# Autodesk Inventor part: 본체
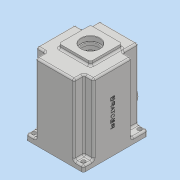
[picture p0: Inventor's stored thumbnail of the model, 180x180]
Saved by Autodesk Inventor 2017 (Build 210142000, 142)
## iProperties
Part Number: 본체
Material: 일반
Document SubType Name: Modeling
Designer: MRC
Density: 1 g/cm^3
Appearance: 기본값
Author: MRC
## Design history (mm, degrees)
sketch "스케치1"
  geometry: L1 (-49, 60)-(49, 60); L2 (49, 60)-(49, -50); L3 (49, -50)-(-49, -50); L4 (-49, -50)-(-49, 60); 2 further points
  constraints: 8 end point, 2 parallel, 1 horizontal, 1 midpoint, 1 perpendicular, 1 vertical alignment
  dimensions: "d0" = 50 distance from line of L3 point (0, 0); "d1" = 110 distance of L1.end L2.end; "d2" = 98 distance of L2.end L3.end
extrude "돌출1" new body sketch "스케치1" stored distance "d3" = 130; taper "d4" = 0 deg
sketch "스케치2"
  geometry: L1 (49, 60)-(-49, 60) reference; L2 (-49, -50)-(49, -50) reference; L3 (49, -50)-(49, 60) reference; L4 (33, 60)-(33, 33); L5 (33, 33)-(49, 33); L6 (49, -33)-(33, -33); L7 (33, -33)-(33, -50); 1 further point
  constraints: 8 end point, 4 point on line, 3 perpendicular, 1 horizontal
  dimensions: "d5" = 16 distance of L4.end L5.end; "d6" = 27 distance of L4.start L4.end; "d7" = 17 distance of L6.end L7.end; "d8" = 16 distance of L6.start L6.end
extrude "돌출2" cut sketch "스케치2" distance "d9" = 120; taper "d10" = 0 deg
sketch "스케치3"
  geometry: L1 (-27, 38)-(27, 38); L2 (27, 38)-(27, -16); L3 (27, -16)-(-27, -16); L4 (-27, -16)-(-27, 38); 2 further points
  constraints: 8 end point, 2 parallel, 1 horizontal, 1 midpoint, 1 perpendicular, 1 vertical alignment
  dimensions: "d87" = 54 distance of L2.end L3.end; "d88" = 54 distance of L1.end L2.end
extrude "돌출12" join sketch "스케치3" distance "d90" = 7; taper "d91" = 0 deg
sketch "스케치4"
  geometry: L1 (-26, 53)-(26, 53); L2 (26, 53)-(26, 36.729); L3 (-26, 53)-(-26, 36.729); A1 r 45 centre (0, 0) between (-26, 36.729) and (26, 36.729); 2 further points
  constraints: 6 end point, 2 point on circle, 2 vertical, 1 centre point, 1 coincident, 1 horizontal, 1 midpoint, 1 vertical alignment
  dimensions: "d15" = 90 diameter of A1; "d16" = 52 distance of L1.start L1.end; "d17" = 53 distance from line of point (0, 0) L1
extrude "돌출4" cut sketch "스케치4" distance "d18" = 9; taper "d19" = 0 deg
sketch "스케치5"
  geometry: L1 (-26, 53)-(26, 53) reference; L2 (-26, 36.729)-(-26, 53) reference; L3 (26, 53)-(26, 36.729) reference; L4 (-26, 53)-(26, 53) reference; L5 (-26, 36.729)-(-26, 53) reference; L6 (26, 53)-(26, 36.729) reference; L7 (23, 50)-(-23, 50); L8 (-23, 50)-(-23, 35.143); L9 (23, 35.143)-(23, 50); A1 r 45 centre (0, 0) between (-26, 36.729) and (26, 36.729) reference; A2 r 45 centre (0, 0) between (-26, 36.729) and (26, 36.729) reference; A3 r 42 centre (0, 0) between (-23, 35.143) and (23, 35.143)
  constraints: 6 end point, 2 point on circle, 1 centre point, 3 other
  dimensions: "d20" = 3 distance between parallel lines of L1 L7
extrude "돌출5" cut sketch "스케치5" distance "d21" = 112; taper "d22" = 0 deg
sketch "스케치6"
  geometry: A1 r 42 centre (0, 0) between (-23, 35.143) and (23, 35.143) reference; A2 r 21 centre (0, 11) between (8.978, -7.984) and (-8.978, -7.984); A3 r 15 centre (0, -20) between (-8.978, -7.984) and (8.978, -7.984)
  constraints: 4 point on circle, 2 centre point, 2 vertical alignment
  dimensions: "d23" = 42 diameter of A2; "d24" = 11 distance of A1.centre A2.centre; "d25" = 30 diameter of A3; "d26" = 20 distance of A3.centre A1.centre
extrude "돌출6" join sketch "스케치6" distance "d27" = 7; taper "d28" = 0 deg
sketch "스케치7"
  geometry: C1 r 17.5 at (0, 11); A1 r 21 centre (0, 11) between (8.978, -7.984) and (-8.978, -7.984) reference; 1 further point
  constraints: 1 centre point, 1 coincident
  dimensions: "d29" = 35 diameter of C1
extrude "돌출7" cut sketch "스케치7" distance "d30" = 10; taper "d31" = 0 deg
sketch "스케치8"
  geometry: C1 r 17.5 at (0, 0) reference; C2 r 14 at (0, 0); 1 further point
  constraints: 1 centre point, 1 coincident
  dimensions: "d32" = 28 diameter of C2
extrude "돌출8" cut sketch "스케치8" stored distance "d33" = 10; taper "d34" = 0 deg
sketch "스케치9"
  geometry: C1 r 11 at (0, -20); A1 r 15 centre (0, -20) between (-8.978, -7.984) and (8.978, -7.984) reference; 1 further point
  constraints: 1 centre point, 1 coincident
  dimensions: "d35" = 22 diameter of C1
extrude "돌출9" cut sketch "스케치9" distance "d36" = 7; taper "d37" = 0 deg
sketch "스케치10"
  geometry: C1 r 11 at (0, 0) reference; C2 r 9.5 at (0, 0); 1 further point
  constraints: 1 centre point, 1 coincident
  dimensions: "d38" = 19 diameter of C2
extrude "돌출10" cut sketch "스케치10" distance "d39" = 3; taper "d40" = 0 deg
fillet "모깎기1" dims "d41" = 3
fillet "모깎기2" dims "d42" = 0.3
chamfer "모따기1" distance "d43" = 1; stored, may be unused: second distance "d44" = 2, angle "d45" = 45 deg
chamfer "모따기2" distance "d46" = 1; stored, may be unused: second distance "d47" = 2, angle "d48" = 45 deg
fillet "모깎기3" dims "d49" = 0.3
sketch "스케치13"
  geometry: L1 (-23, 35.143)-(-23, 50) reference; L2 (23, 50)-(23, 35.143) reference; L3 (-35.777, 4)-(-41.809, 4); L4 (-35.777, -4)-(-41.809, -4); A1 r 36 centre (0, 0) between (-36, 0) and (-35.777, 4); A2 r 4 centre (-36, 0) between (-36, -4) and (-36, 4); A3 r 42 centre (0, 0) between (-41.809, 4) and (-41.809, -4); A4 r 42 centre (0, 0) between (23, 35.143) and (-23, 35.143); 2 further points
  constraints: 9 point on circle, 6 end point, 4 centre point, 2 coincident, 2 horizontal, 2 point on line, 2 tangent, 1 horizontal alignment
  dimensions: "d57" = 72 diameter of A1; "d58" = 8 diameter of A2
extrude "돌출11" join sketch "스케치13" stored distance "d60" = 3; taper "d61" = 0 deg
hole "구멍1" diameter "d64" = 3.242; stored, may be unused: countersink angle "d68" = 90 deg, drill point angle "d70" = 118 deg; dims "d62" = 10, "d63" = 10, "d65" = 7, "d66" = 4, "d67" = 2, "d69" = 9
hole "구멍2" diameter "d73" = 3.242; stored, may be unused: countersink angle "d77" = 90 deg, drill point angle "d79" = 118 deg; dims "d71" = 10, "d72" = 10, "d74" = 7, "d75" = 4, "d76" = 2, "d78" = 9
fillet "모깎기6" dims "d80" = 6
fillet "모깎기7" dims "d81" = 3
fillet "모깎기8" dims "d82" = 3
chamfer "모따기3" distance "d83" = 1; stored, may be unused: second distance "d84" = 2, angle "d85" = 45 deg
fillet "모깎기9" dims "d86" = 3
sketch "스케치15"
  geometry: L1 (11, 63.7)-(11, 72); L2 (11, 72)-(27.462, 72); L3 (-3, 72)-(25, 72) reference; L4 (27.462, 72)-(27, 71.2); L5 (27, 71.2)-(27, 63.7); L6 (27, 63.7)-(11, 63.7); L7 (38, 72)-(-16, 72) reference; 1 further point
  constraints: 10 end point, 1 collinear, 1 midpoint, 1 parallel, 1 perpendicular, 1 point on line, 1 vertical
  dimensions: "d94" = 8.3 distance between parallel lines of L2 L6; "d95" = 0.8 vertical distance of L2.end L4.end; "d96" = 30 deg angle of L5 L4; "d97" = 32 diameter of L5 L1
revolve "회전2" sketch "스케치15" stored, may be unused: angle "d98" = 90 deg
fillet "모깎기10" dims "d99" = 0.3
fillet "모깎기11" dims "d100" = 3
fillet "모깎기12" dims "d101" = 3
fillet "모깎기13" dims "d102" = 3
sketch "스케치16"
  geometry: L1 (-49, 57)-(-49, -47) reference; L2 (46, 60)-(-46, 60) reference; L3 (-46, -50)-(46, -50) reference; L4 (49, -47)-(49, 57) reference; C1 r 3.5 at (-42, 53); C2 r 3.5 at (-42, -43); C3 r 3.5 at (42, -43); C4 r 3.5 at (42, 53)
  constraints: 4 centre point
  dimensions: "d104" = 7 diameter of C1; "d105" = 7 distance from line of L2 C1.centre; "d106" = 7 distance from line of L1 C1.centre; "d109" = 7 diameter of C2; "d110" = 7 diameter of C3; "d111" = 7 diameter of C4; "d112" = 7 distance from line of L3 C2.centre; "d113" = 7 distance from line of L1 C2.centre; "d114" = 7 distance from line of L3 C3.centre; "d115" = 7 distance from line of C3.centre L4; "d116" = 7 distance from line of L2 C4.centre; "d117" = 7 distance from line of L4 C4.centre
extrude "돌출14" cut sketch "스케치16" stored distance "d118" = 7; taper "d119" = 0 deg
sketch "스케치17"
  geometry: L1 (0, 0)-(92, 0) reference; C1 r 22.5 at (46, -40); 2 further points
  constraints: 1 centre point, 1 midpoint, 1 vertical alignment
  dimensions: "d120" = 45 diameter of C1; "d121" = 40 distance from line of L1 C1.centre
extrude "돌출15" join sketch "스케치17" distance "d122" = 10; taper "d123" = 0 deg
sketch "스케치18"
  geometry: C1 r 22.5 at (46, -40) reference; C2 r 15 at (46, -89); 1 further point
  constraints: 1 centre point, 1 vertical alignment
  dimensions: "d124" = 30 diameter of C2; "d125" = 49 distance of C2.centre C1.centre
extrude "돌출16" join sketch "스케치18" distance "d126" = 5; taper "d127" = 0 deg
hole "구멍3" diameter "d130" = 33.376; stored, may be unused: countersink angle "d134" = 90 deg, drill point angle "d136" = 118 deg; dims "d128" = 10, "d129" = 10, "d131" = 70, "d132" = 4, "d133" = 2, "d135" = 77.3
sketch "스케치20"
  geometry: C1 r 15 at (20, 80) reference; C2 r 15 at (20, 80); 1 further point
  constraints: 1 centre point, 1 coincident
  dimensions: "d137" = 30 diameter of C2
extrude "돌출17" cut sketch "스케치20" distance "d138" = 5; taper "d139" = 0 deg
chamfer "모따기4" distance "d140" = 1; stored, may be unused: second distance "d141" = 2, angle "d142" = 45 deg
sketch "스케치21"
  geometry: C1 r 15 at (0, 0) reference; C2 r 10 at (0, 0); 1 further point
  constraints: 1 centre point, 1 coincident
  dimensions: "d143" = 20 diameter of C2
extrude "돌출18" cut sketch "스케치21" stored distance "d144" = 5; taper "d145" = 0 deg
fillet "모깎기15" dims "d146" = 3
sketch "스케치22"
  geometry: L1 (-130, 104)-(-130, 83) reference; 2 further points
  constraints: 2 coincident, 1 other
  dimensions: "d147" = 65 distance from line of L1 point (-65, 47) (derived)
feature "엠보싱1" sketch "스케치22" dims "d10" = 0, "d148" = 0.5, "d149" = 0
node "솔리드1"
mirror "미러1"
mirror "미러2"
node "투영된 루프1"
